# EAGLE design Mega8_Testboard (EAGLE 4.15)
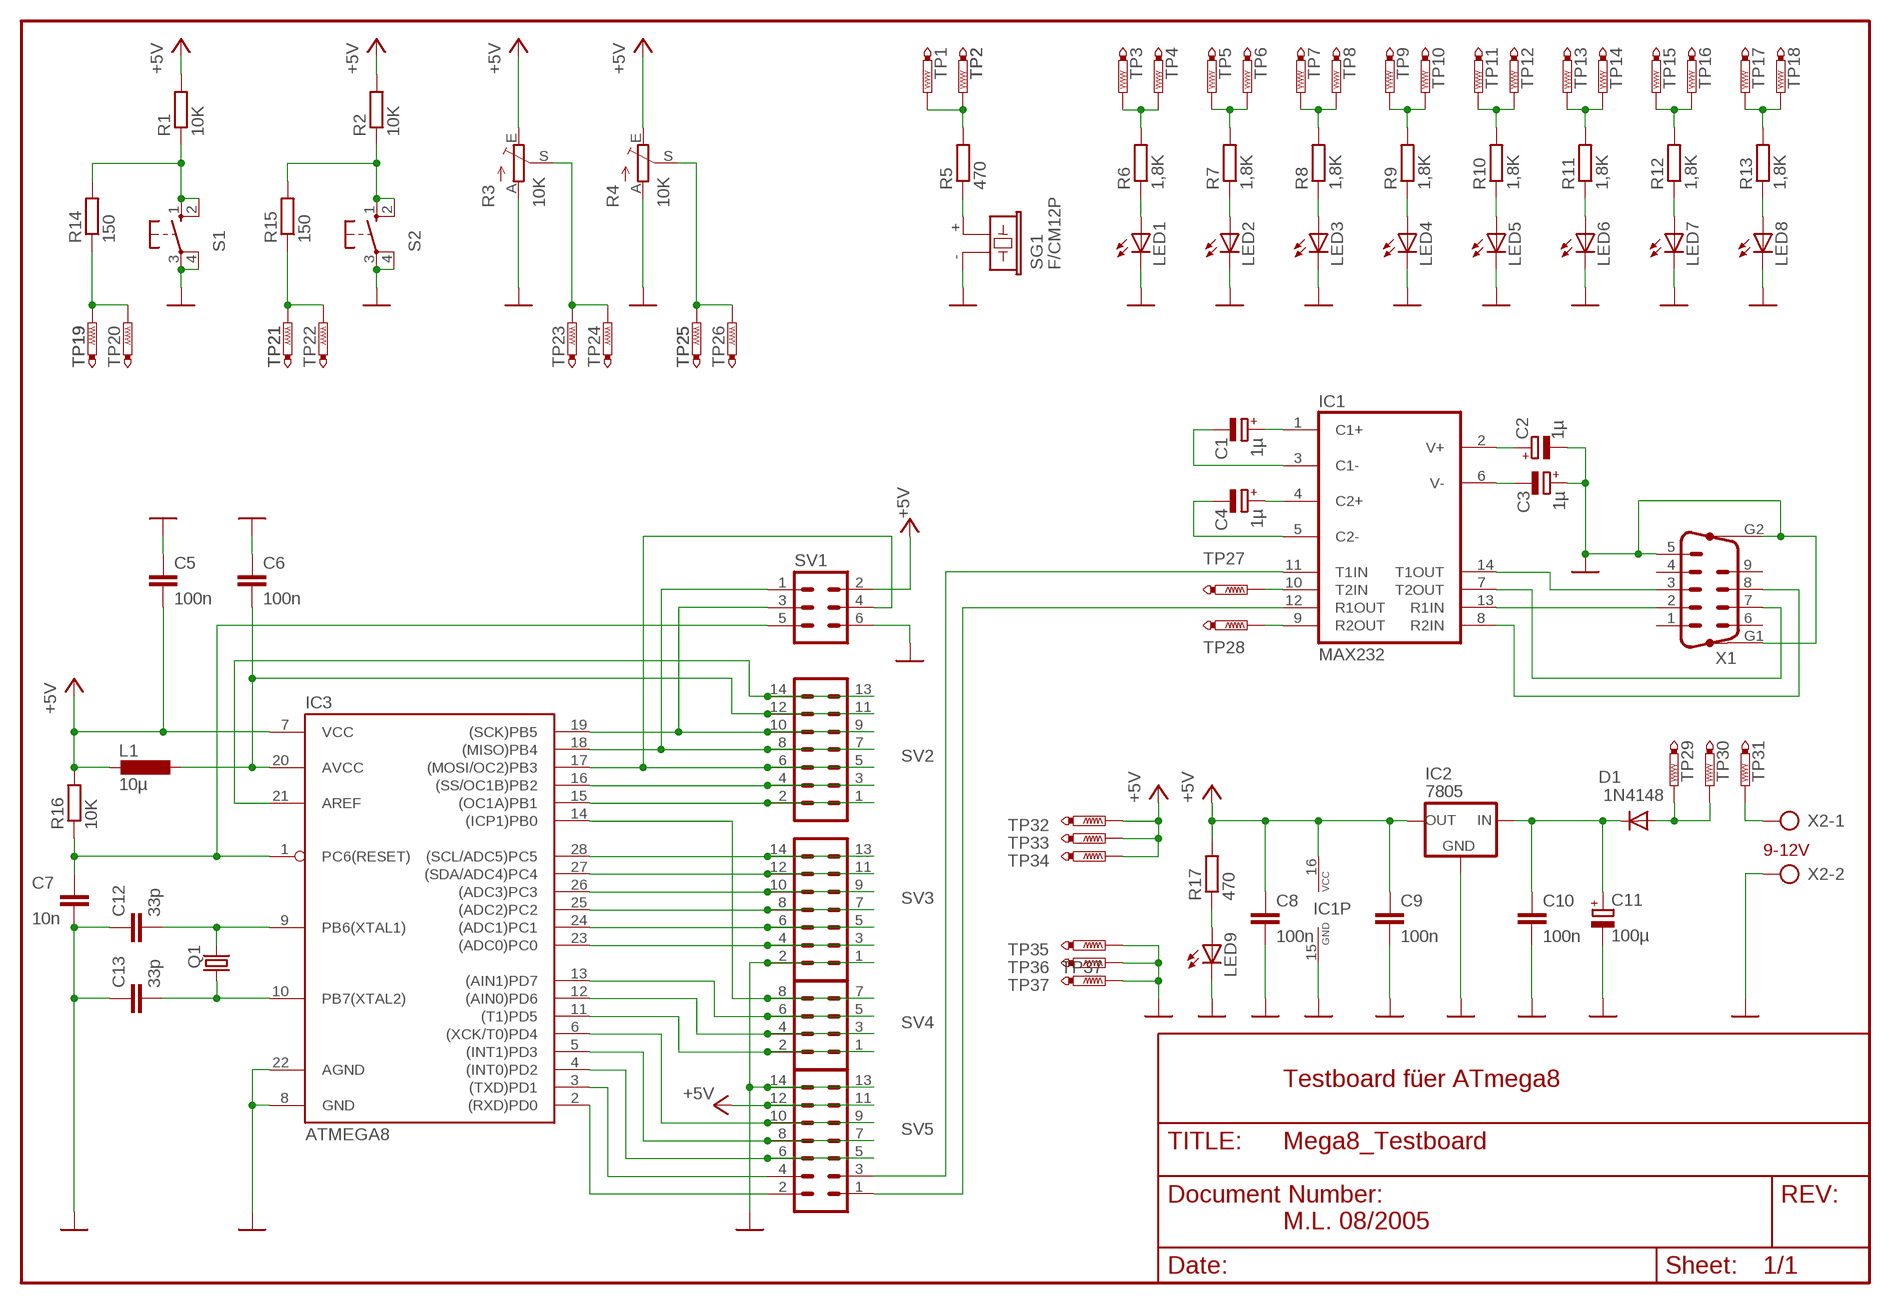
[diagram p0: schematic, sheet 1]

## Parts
C1  1µ  CPOL-EUE2-5  [E2-5]
C2  1µ  CPOL-EUE2-5  [E2-5]
C3  1µ  CPOL-EUE2-5  [E2-5]
C4  1µ  CPOL-EUE2-5  [E2-5]
C5  100n  C-EU050-025X075  [C050-025X075]
C6  100n  C-EU050-025X075  [C050-025X075]
C7  10n  C-EU050-025X075  [C050-025X075]
C8  100n  C-EU050-025X075  [C050-025X075]
C9  100n  C-EU050-025X075  [C050-025X075]
C10  100n  C-EU050-025X075  [C050-025X075]
C11  100µ  CPOL-EUE5-10.5  [E5-10,5]
C12  33p  C-EU050-025X075  [C050-025X075]
C13  33p  C-EU050-025X075  [C050-025X075]
D1  1N4148  [DO35-10]
IC1  MAX232  [DIL16]
IC2  7805  78XXS  [78XXS]
IC3  ATMEGA8  [28P_DIL]
L1  10µ  L-EU0207/10  [0207/10]
LED1  LEDSFH482  [SFH482]
LED2  LEDSFH482  [SFH482]
LED3  LEDSFH482  [SFH482]
LED4  LEDSFH482  [SFH482]
LED5  LEDSFH482  [SFH482]
LED6  LEDSFH482  [SFH482]
LED7  LEDSFH482  [SFH482]
LED8  LEDSFH482  [SFH482]
LED9  LEDSFH482  [SFH482]
Q1  CRYTALHC49S  [HC49/S]
R1  10K  R-EU_0207/10  [0207/10]
R2  10K  R-EU_0207/10  [0207/10]
R3  10K  TRIM_EU-CA9V  [CA9V]
R4  10K  TRIM_EU-CA9V  [CA9V]
R5  470  R-EU_0207/10  [0207/10]
R6  1,8K  R-EU_0207/10  [0207/10]
R7  1,8K  R-EU_0207/10  [0207/10]
R8  1,8K  R-EU_0207/10  [0207/10]
R9  1,8K  R-EU_0207/10  [0207/10]
R10  1,8K  R-EU_0207/10  [0207/10]
R11  1,8K  R-EU_0207/10  [0207/10]
R12  1,8K  R-EU_0207/10  [0207/10]
R13  1,8K  R-EU_0207/10  [0207/10]
R14  150  R-EU_0207/10  [0207/10]
R15  150  R-EU_0207/10  [0207/10]
R16  10K  R-EU_0207/10  [0207/10]
R17  470  R-EU_0207/10  [0207/10]
S1  40-XX  [B3F-40XX]
S2  40-XX  [B3F-40XX]
SG1  F/CM12P  [F/CM12P]
SV1  MA03-2  [MA03-2]
SV2  MA07-2  [MA07-2]
SV3  MA07-2  [MA07-2]
SV4  MA04-2  [MA04-2]
SV5  MA07-2  [MA07-2]
TP1  PTR1PAD1-13  [P1-13]
TP2  PTR1PAD1-13  [P1-13]
TP3  PTR1PAD1-13  [P1-13]
TP4  PTR1PAD1-13  [P1-13]
TP5  PTR1PAD1-13  [P1-13]
TP6  PTR1PAD1-13  [P1-13]
TP7  PTR1PAD1-13  [P1-13]
TP8  PTR1PAD1-13  [P1-13]
TP9  PTR1PAD1-13  [P1-13]
TP10  PTR1PAD1-13  [P1-13]
TP11  PTR1PAD1-13  [P1-13]
TP12  PTR1PAD1-13  [P1-13]
TP13  PTR1PAD1-13  [P1-13]
TP14  PTR1PAD1-13  [P1-13]
TP15  PTR1PAD1-13  [P1-13]
TP16  PTR1PAD1-13  [P1-13]
TP17  PTR1PAD1-13  [P1-13]
TP18  PTR1PAD1-13  [P1-13]
TP19  PTR1PAD1-13  [P1-13]
TP20  PTR1PAD1-13  [P1-13]
TP21  PTR1PAD1-13  [P1-13]
TP22  PTR1PAD1-13  [P1-13]
TP23  PTR1PAD1-13  [P1-13]
TP24  PTR1PAD1-13  [P1-13]
TP25  PTR1PAD1-13  [P1-13]
TP26  PTR1PAD1-13  [P1-13]
TP27  PTR1PAD1-13  [P1-13]
TP28  PTR1PAD1-13  [P1-13]
TP29  PTR1PAD1-13  [P1-13]
TP30  PTR1PAD1-13  [P1-13]
TP31  PTR1PAD1-13  [P1-13]
TP32  PTR1PAD1-13  [P1-13]
TP33  PTR1PAD1-13  [P1-13]
TP34  PTR1PAD1-13  [P1-13]
TP35  PTR1PAD1-13  [P1-13]
TP36  PTR1PAD1-13  [P1-13]
TP37  PTR1PAD1-13  [P1-13]
X1  M09HP  [M09HP]
X2  AK300/2  [AK300/2]

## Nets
+5V: C5.2 C8.1 C9.1 IC1.16(VCC) IC2.OUT IC3.7(VCC) L1.2 R1.2 R2.2 R3.E R4.E R16.2 R17.2 SV1.2 SV5.11 SV5.12 TP32.1(TP) TP33.1(TP) TP34.1(TP)
AREF: IC3.21(AREF) SV2.13 SV2.14
AVCC: C6.2 IC3.20(AVCC) L1.1 SV2.11 SV2.12
GND: C2.- C3.+ C5.1 C6.1 C7.2 C8.2 C9.2 C10.2 C11.- C12.1 C13.1 IC1.15(GND) IC2.GND IC3.8(GND) IC3.22(AGND) LED1.K(C) LED2.K(C) LED3.K(C) LED4.K(C) LED5.K(C) LED6.K(C) LED7.K(C) LED8.K(C) LED9.K(C) R3.A R4.A S1.3(P) S1.4(P1) S2.3(P) S2.4(P1) SG1.- SV1.6 SV3.1 SV3.2 SV5.13 SV5.14 TP35.1(TP) TP36.1(TP) TP37.1(TP) X1.5 X1.G1 X1.G2 X2.2
N$1: C1.+ IC1.1(C1+)
N$2: C1.- IC1.3(C1-)
N$3: C4.+ IC1.4(C2+)
N$4: C4.- IC1.5(C2-)
N$5: C2.+ IC1.2(V+)
N$6: C3.- IC1.6(V-)
N$7: IC1.14(T1OUT) X1.3
N$8: IC1.13(R1IN) X1.2
N$9: R3.S TP23.1(TP) TP24.1(TP)
N$10: LED9.A R17.1
N$11: C10.1 C11.+ D1.C IC2.IN
N$12: TP31.1(TP) X2.1
N$13: D1.A TP29.1(TP) TP30.1(TP)
N$14: R4.S TP25.1(TP) TP26.1(TP)
N$15: R6.2 TP3.1(TP) TP4.1(TP)
N$16: LED1.A R6.1
N$17: LED2.A R7.1
N$18: LED3.A R8.1
N$19: R7.2 TP5.1(TP) TP6.1(TP)
N$20: LED4.A R9.1
N$21: LED5.A R10.1
N$22: LED6.A R11.1
N$23: R8.2 TP7.1(TP) TP8.1(TP)
N$24: LED7.A R12.1
N$25: LED8.A R13.1
N$26: IC1.7(T2OUT) X1.7
N$27: R9.2 TP9.1(TP) TP10.1(TP)
N$28: IC1.10(T2IN) TP27.1(TP)
N$29: IC1.8(R2IN) X1.8
N$30: IC1.9(R2OUT) TP28.1(TP)
N$31: R10.2 TP11.1(TP) TP12.1(TP)
N$32: R11.2 TP13.1(TP) TP14.1(TP)
N$33: R12.2 TP15.1(TP) TP16.1(TP)
N$34: R5.1 SG1.+
N$35: R13.2 TP17.1(TP) TP18.1(TP)
N$36: IC1.12(R1OUT) SV5.1
N$37: IC1.11(T1IN) SV5.3
N$40: R14.1 TP19.1(TP) TP20.1(TP)
N$41: R15.1 TP21.1(TP) TP22.1(TP)
N$45: R1.1 R14.2 S1.1(S) S1.2(S1)
N$47: R2.1 R15.2 S2.1(S) S2.2(S1)
N$48: R5.2 TP1.1(TP) TP2.1(TP)
N$50: IC3.2((RXD)PD0) SV5.2
N$51: C12.2 IC3.9(PB6(XTAL1)) Q1.2
N$52: C13.2 IC3.10(PB7(XTAL2)) Q1.1
N$53: IC3.3((TXD)PD1) SV5.4
N$54: IC3.4((INT0)PD2) SV5.5 SV5.6
N$55: IC3.5((INT1)PD3) SV5.7 SV5.8
N$56: IC3.6((XCK/T0)PD4) SV5.9 SV5.10
N$57: IC3.11((T1)PD5) SV4.1 SV4.2
N$58: C7.1 IC3.1(PC6(RESET)) R16.1 SV1.5
N$59: IC3.12((AIN0)PD6) SV4.3 SV4.4
N$60: IC3.13((AIN1)PD7) SV4.5 SV4.6
N$61: IC3.14((ICP1)PB0) SV4.7 SV4.8
N$62: IC3.15((OC1A)PB1) SV2.1 SV2.2
N$63: IC3.16((SS/OC1B)PB2) SV2.3 SV2.4
N$64: IC3.17((MOSI/OC2)PB3) SV1.4 SV2.5 SV2.6
N$65: IC3.18((MISO)PB4) SV1.1 SV2.7 SV2.8
N$66: IC3.19((SCK)PB5) SV1.3 SV2.9 SV2.10
N$67: IC3.23((ADC0)PC0) SV3.3 SV3.4
N$69: IC3.24((ADC1)PC1) SV3.5 SV3.6
N$70: IC3.25((ADC2)PC2) SV3.7 SV3.8
N$71: IC3.26((ADC3)PC3) SV3.9 SV3.10
N$72: IC3.27((SDA/ADC4)PC4) SV3.11 SV3.12
N$73: IC3.28((SCL/ADC5)PC5) SV3.13 SV3.14
Unconnected: X1.1 X1.4 X1.6 X1.9

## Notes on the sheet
- 9-12V
- Testboard füer ATmega8
- M.L. 08/2005

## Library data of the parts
C1-C4 C11 = RCL:CPOL-EU: POLARIZED CAPACITOR, European symbol
C5-C10 C12 C13 = RCL:C-EU: CAPACITOR, European symbol
D1 = diode:1N4148: DIODE
IC1 = maxim:MAX232: RS232 TRANSEIVER
IC2 = v-reg:78XXS: VOLTAGE REGULATOR
IC3 = MANNI:ATMEGA8: 8-bit AVR with 8KBytes In-System Programmable Flash ATmega8(L)
L1 = RCL:L-EU: INDUCTOR, European symbol
LED1-LED9 = led:LED: LED
Q1 = crystal:CRYTAL: CRYSTAL
R1 R2 R5-R17 = RCL:R-EU_: RESISTOR, European symbol
R3 R4 = pot:TRIM_EU-: POTENTIOMETER
S1 S2 = switch-omron:40-XX: OMRON SWITCH
SG1 = buzzer:F/CM12P: BUZZER
SV1 = con-lstb:MA03-2: PIN HEADER
SV2 SV3 SV5 = con-lstb:MA07-2: PIN HEADER
SV4 = con-lstb:MA04-2: PIN HEADER
TP1-TP37 = testpad:PTR1: TEST PIN
X1 = con-subd:M09HP: SUB-D
X2 = con-ptr500:AK300/2: CONNECTOR

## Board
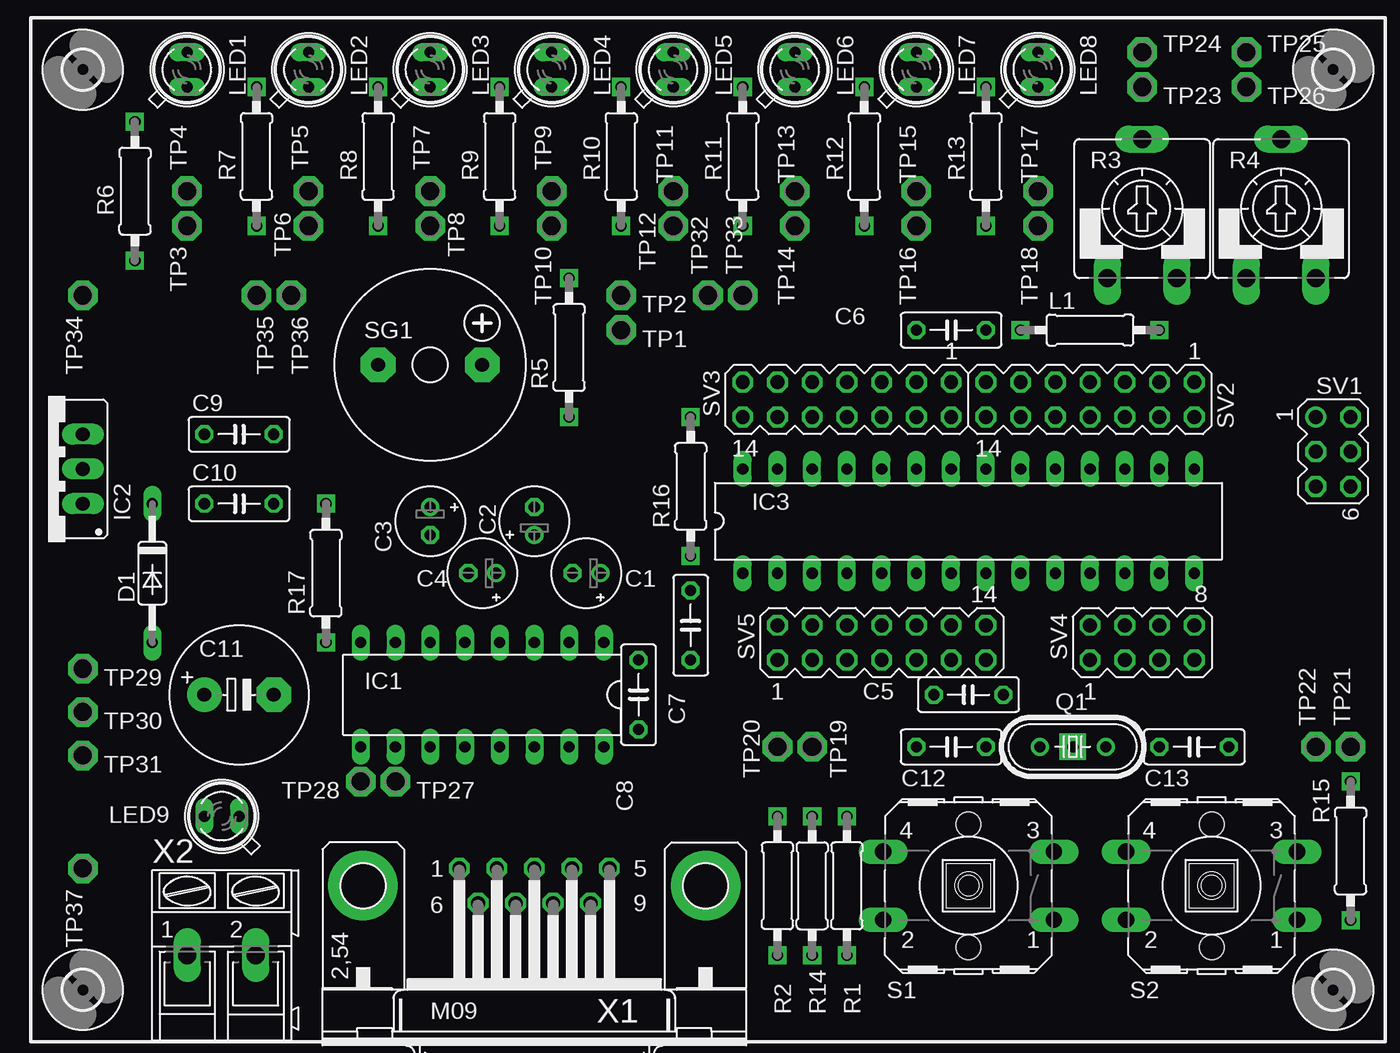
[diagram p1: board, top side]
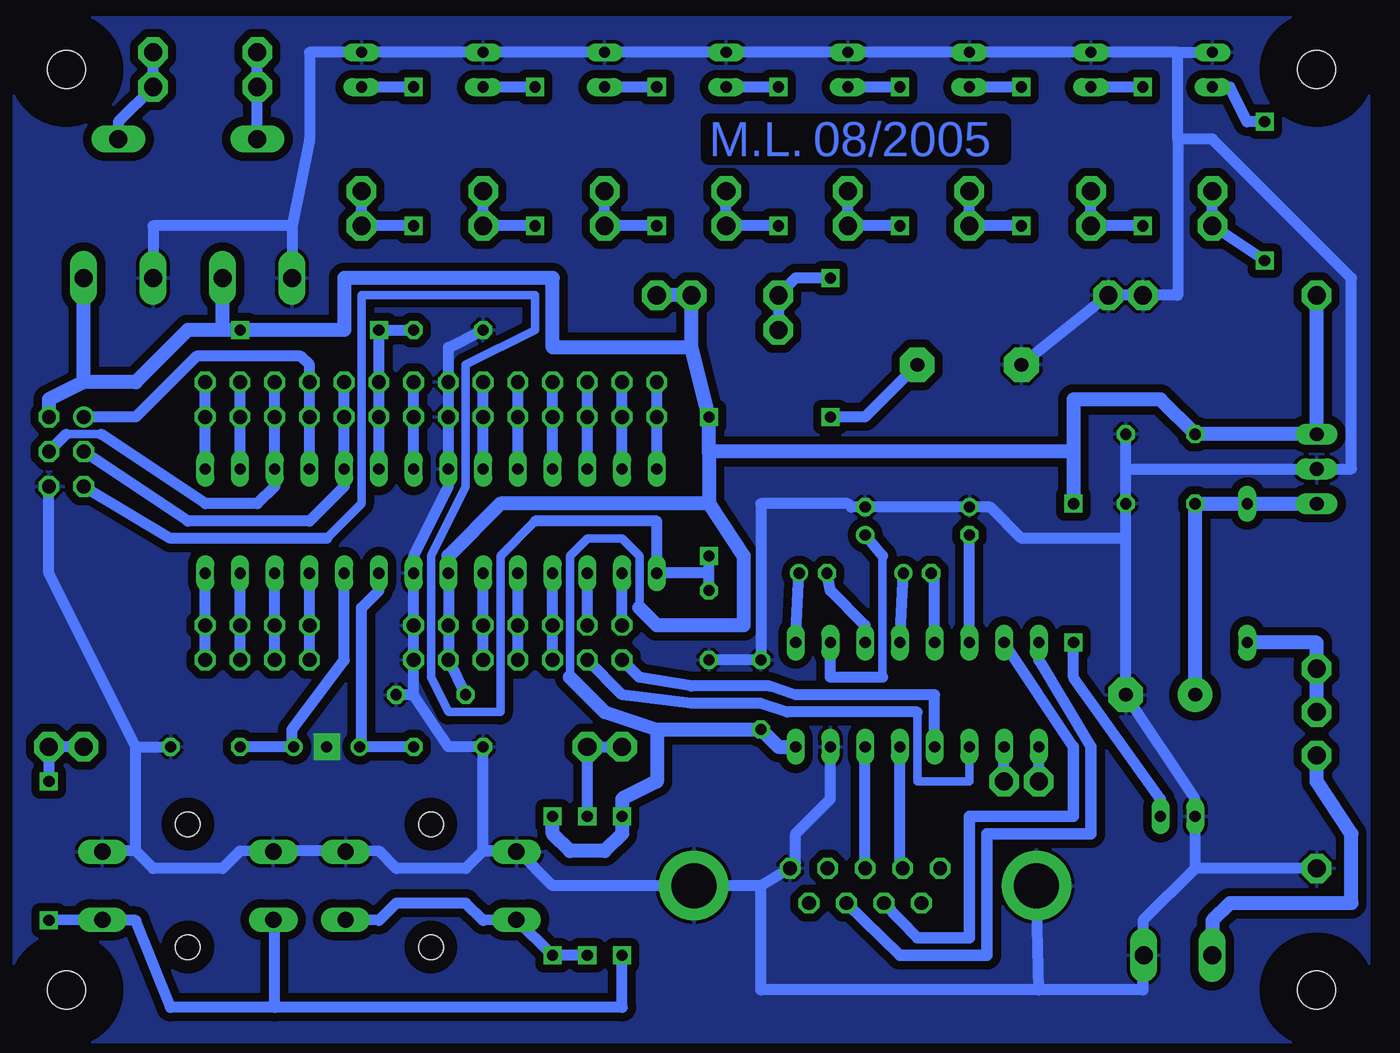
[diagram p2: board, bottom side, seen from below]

No outline drawn. Coordinates in mm, seen from the top.
Copper layers (1*16): Top 0.035mm / dielectric 1.5mm / Bottom 0.035mm
Design rules "default": minimum track width 10mil, minimum drill 24mil, track to track 8mil, track to pad 8mil, pad to pad 8mil, via to via 8mil, smd to smd 8mil, copper to edge 40mil, drill to drill 8mil, minimum pad ring 10mil, minimum via ring 8mil, stop-mask expansion 4mil, vias tented up to drill 0mil, thermal gap 10mil

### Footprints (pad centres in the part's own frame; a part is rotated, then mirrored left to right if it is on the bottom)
E2-5 = drill 0.813 pad 1.27 round: + -1.016,0 | drill 0.813 pad 1.27 octagon: - 1.016,0
C050-025X075 = drill 0.813 octagon: 1 -2.54,0; 2 2.54,0
E5-10,5 = drill 1.016 pad 2.54 round: + -2.54,0 | drill 1.016 pad 2.54 octagon: - 2.54,0
DO35-10 = drill 0.813 long: A 5.08,0; C -5.08,0
DIL16 = drill 0.813 long: 1 -8.89,-3.81; 2 -6.35,-3.81; 3 -3.81,-3.81; 4 -1.27,-3.81; 5 1.27,-3.81; 6 3.81,-3.81; 7 6.35,-3.81; 8 8.89,-3.81; 9 8.89,3.81; 10 6.35,3.81; 11 3.81,3.81; 12 1.27,3.81; 13 -1.27,3.81; 14 -3.81,3.81; 15 -6.35,3.81; 16 -8.89,3.81
78XXS = drill 1.016 long: GND 0,-2.54; IN -2.54,-2.54; OUT 2.54,-2.54
28P_DIL = drill 0.813 long: 1 -15.24,-3.81; 2 -12.7,-3.81; 3 -10.16,-3.81; 4 -7.62,-3.81; 5 -5.08,-3.81; 6 -2.54,-3.81; 7 0,-3.81; 8 2.54,-3.81; 9 5.08,-3.81; 10 7.62,-3.81; 11 10.16,-3.81; 12 12.7,-3.81; 13 15.24,-3.81; 14 17.78,-3.81; 15 17.78,3.81; 16 15.24,3.81; 17 12.7,3.81; 18 10.16,3.81; 19 7.62,3.81; 20 5.08,3.81; 21 2.54,3.81; 22 0,3.81; 23 -2.54,3.81; 24 -5.08,3.81; 25 -7.62,3.81; 26 -10.16,3.81; 27 -12.7,3.81; 28 -15.24,3.81
0207/10 = drill 0.813 square: 1 -5.08,0; 2 5.08,0
SFH482 = drill 0.813 long: A -1.27,0; K 1.27,0
HC49/S = drill 0.813 round: 1 -2.413,0; 2 2.413,0
CA9V = drill 1.321 long: A -2.54,-5.08; E 2.54,-5.08; S 0,5.08
B3F-40XX = drill 1.194 long: 1 -6.248,2.489; 2 6.248,2.489; 3 -6.248,-2.489; 4 6.248,-2.489 | hole 1.803: 0,-4.496; 0,4.496
F/CM12P = drill 1.016 pad 2.54 octagon: + 3.81,0; - -3.81,0
MA03-2 = drill 1.016 round: 1 -2.54,-1.27 | drill 1.016 octagon: 2 -2.54,1.27; 3 0,-1.27; 4 0,1.27; 5 2.54,-1.27; 6 2.54,1.27
MA07-2 = drill 1.016 octagon: 1 -7.62,-1.27; 2 -7.62,1.27; 3 -5.08,-1.27; 4 -5.08,1.27; 5 -2.54,-1.27; 6 -2.54,1.27; 7 0,-1.27; 8 0,1.27; 9 2.54,-1.27; 10 2.54,1.27; 11 5.08,-1.27; 12 5.08,1.27; 13 7.62,-1.27; 14 7.62,1.27
MA04-2 = drill 1.016 octagon: 1 -3.81,-1.27; 2 -3.81,1.27; 3 -1.27,-1.27; 4 -1.27,1.27; 5 1.27,-1.27; 6 1.27,1.27; 7 3.81,-1.27; 8 3.81,1.27
P1-13 = drill 1.321 pad 2.159 octagon: 1 0,0
2,8 = hole 2.8: 0,0
M09HP = drill 1.016 octagon: 1 -5.486,1.27; 2 -2.743,1.27; 3 0,1.27; 4 2.743,1.27; 5 5.486,1.27; 6 -4.115,-1.27; 7 -1.372,-1.27; 8 1.372,-1.27; 9 4.115,-1.27 | drill 3.302 pad 5.08 round: G1 -12.522,0; G2 12.522,0
AK300/2 = drill 1.321 long: 1 -2.515,0; 2 2.489,0

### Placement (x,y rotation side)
C1  40.64,34.29 180 top
C2  36.83,38.1 90 top
C3  29.21,38.1 270 top
C4  33.02,34.29 180 top
C5  68.58,25.4 180 top
C6  67.31,52.07 0 top
C7  48.26,30.48 270 top
C8  44.45,25.4 90 top
C9  15.24,44.45 0 top
C10  15.24,39.37 0 top
C11  15.24,25.4 0 top
C12  67.31,21.59 0 top
C13  85.09,21.59 180 top
D1  8.89,34.29 270 top
IC1  33.02,25.4 180 top
IC2  1.27,41.91 90 top
IC3  67.31,38.1 0 top
L1  77.47,52.07 0 top
LED1  11.43,71.12 90 top
LED2  20.32,71.12 90 top
LED3  29.21,71.12 90 top
LED4  38.1,71.12 90 top
LED5  46.99,71.12 90 top
LED6  55.88,71.12 90 top
LED7  64.77,71.12 90 top
LED8  73.66,71.12 90 top
LED9  13.97,16.51 180 top
Q1  76.2,21.59 180 top
R1  59.69,11.43 90 top
R2  54.61,11.43 90 top
R3  81.28,60.96 0 top
R4  91.44,60.96 0 top
R5  39.37,50.8 90 top
R6  7.62,62.23 270 top
R7  16.51,64.77 270 top
R8  25.4,64.77 270 top
R9  34.29,64.77 270 top
R10  43.18,64.77 270 top
R11  52.07,64.77 270 top
R12  60.96,64.77 270 top
R13  69.85,64.77 270 top
R14  57.15,11.43 270 top
R15  96.52,13.97 270 top
R16  48.26,40.64 90 top
R17  21.59,34.29 90 top
S1  68.58,11.43 180 top
S2  86.36,11.43 180 top
SG1  29.21,49.53 0 top
SV1  95.25,43.18 270 top
SV2  77.47,46.99 180 top
SV3  59.69,46.99 180 top
SV4  81.28,29.21 0 top
SV5  62.23,29.21 0 top
TP1  43.18,52.07 180 top
TP2  43.18,54.61 180 top
TP3  11.43,59.69 180 top
TP4  11.43,62.23 180 top
TP5  20.32,62.23 180 top
TP6  20.32,59.69 180 top
TP7  29.21,62.23 180 top
TP8  29.21,59.69 180 top
TP9  38.1,62.23 180 top
TP10  38.1,59.69 180 top
TP11  46.99,62.23 180 top
TP12  46.99,59.69 180 top
TP13  55.88,62.23 180 top
TP14  55.88,59.69 180 top
TP15  64.77,62.23 180 top
TP16  64.77,59.69 180 top
TP17  73.66,62.23 180 top
TP18  73.66,59.69 180 top
TP19  57.15,21.59 270 top
TP20  54.61,21.59 270 top
TP21  96.52,21.59 0 top
TP22  93.98,21.59 0 top
TP23  81.28,69.85 270 top
TP24  81.28,72.39 90 top
TP25  88.9,72.39 270 top
TP26  88.9,69.85 270 top
TP27  26.67,19.05 270 top
TP28  24.13,19.05 270 top
TP29  3.81,27.3 0 top
TP30  3.81,24.13 0 top
TP31  3.81,20.95 0 top
TP32  49.53,54.61 270 top
TP33  52.07,54.61 270 top
TP34  3.81,54.61 90 top
TP35  16.51,54.61 90 top
TP36  19.05,54.61 90 top
TP37  3.81,12.7 90 top
U$2  [2,8]  3.81,3.81 0 top
U$3  [2,8]  95.25,3.81 0 top
U$4  [2,8]  95.25,71.12 0 top
U$5  [2,8]  3.81,71.12 0 top
X1  36.83,11.43 0 top
X2  13.97,6.35 0 top

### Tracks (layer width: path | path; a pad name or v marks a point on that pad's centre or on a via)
+5V
  Bottom 0.61: 58.42,26.67 58.42,35.56 57.15,36.83 54.61,36.83 53.34,35.56 53.34,31.75
  Bottom 0.813: 67.31,35.56 IC3.7 SV5.12 SV5.11 C5.2
  Bottom 1.016: IC1.16 43.18,21.59 C8.1 52.07,22.86 | 67.31,35.56 63.5,39.37 48.26,39.37 | 93.98,48.26 96.52,46.99 SV1.2 | 21.59,43.18 48.26,43.18 | 53.34,31.75 52.07,30.48 45.72,30.48 45.72,35.56 48.26,39.37 | 21.59,43.18 21.59,46.99 15.24,46.99 C9.1 IC2.OUT TP34.1 | 21.59,43.18 R17.2 | 48.26,43.18 48.26,39.37 | R1.2 59.69,15.24 58.42,13.97 55.88,13.97 54.61,15.24 R2.2 54.61,17.78 52.07,19.05 52.07,22.86 | TP33.1 TP32.1 49.53,50.8 | 48.26,43.18 R16.2 49.53,50.8 | 83.82,52.07 L1.2 74.93,52.07 74.93,55.88 59.69,55.88 59.69,50.8 49.53,50.8 | 83.82,52.07 R3.E | 93.98,48.26 R4.E | 83.82,52.07 86.36,52.07 90.17,48.26 93.98,48.26 | 58.42,26.67 55.88,24.13 52.07,22.86
AREF
  Bottom 0.813: SV2.13 SV2.14 IC3.21
AVCC
  Bottom 0.813: IC3.20 SV2.12 SV2.11 L1.1 C6.2
GND  (via drill 0.8 pad 1.93)
  Bottom 0.813: 17.78,41.91 C10.2 17.78,36.83 | TP37.1 12.7,12.7 | 12.7,17.78 LED9.K 12.7,12.7 | 16.51,8.89 16.51,6.35 X2.2 16.51,3.81 | 69.85,35.56 67.31,40.64 IC3.22 SV3.2 SV3.1 67.31,50.8 C6.1 | 69.85,35.56 IC3.8 SV5.14 SV5.13 | 64.77,13.97 S1.4 | 90.17,13.97 S2.3 | 90.17,13.97 92.71,13.97 | SV5.13 69.85,35.56 | 62.23,13.97 62.28,13.97 S1.4 | 44.45,11.43 44.45,3.81 24.13,3.81 | 16.51,3.81 24.13,3.81 | 16.51,8.89 16.51,3.81 | 12.7,12.7 16.51,8.89 | 12.7,12.7 12.7,17.78 | 12.7,17.78 C11.- 17.78,36.83 | 90.17,13.97 90.17,21.59 | IC1.15 39.37,17.78 41.91,15.24 41.91,13.11 X1.5 44.45,11.43 | 17.78,36.83 25.4,36.83 27.69,39.12 C3.+ 29.21,39.37 29.46,39.12 C2.- 37.85,39.12 38.1,39.37 44.45,39.37 C8.2 C7.2 | 69.85,25.4 SV5.13 | 69.85,25.4 C5.1 | 64.77,13.97 66.04,12.7 71.12,12.7 72.39,13.97 S1.3 76.2,13.97 80.01,13.97 S2.4 82.55,13.97 83.82,12.7 88.9,12.7 90.17,13.97 | 69.85,25.4 67.31,21.59 C12.1 64.77,13.97 | 90.17,21.59 C13.1 | 62.23,13.97 59.69,11.43 X1.G2 44.45,11.43 | 62.23,13.97 64.77,13.97 | 62.23,13.97 S1.4 | 13.97,72.39 LED2.K LED3.K LED4.K LED5.K LED6.K LED7.K LED8.K 77.47,72.39 77.47,66.04 78.74,59.69 | 13.97,72.39 LED1.K | TP35.1 TP36.1 | TP36.1 SG1.- TP36.1 | 78.74,59.69 88.9,59.69 R4.A | 78.74,59.69 R3.A | 17.78,41.91 C9.2 | 17.78,41.91 IC2.GND 1.27,41.91 1.27,55.88 11.43,66.04 13.97,66.04 | 13.97,66.04 13.97,72.39 | TP35.1 TP36.1 | TP35.1 13.97,54.61 13.97,66.04 | 24.13,3.81 X1.G1 | SV1.6 96.52,34.29 90.17,21.59
  other vias: 76.2,21.59
  pour Bottom (isolate 0.61): 0,0 99.06,0 99.06,74.93 0,74.93
N$1
  Bottom 0.813: IC1.1 C1.+
N$2
  Bottom 0.813: C1.- 39.37,33.02 36.83,30.48 IC1.3
N$3
  Bottom 0.813: IC1.4 C4.+
N$4
  Bottom 0.813: C4.- 31.75,34.29 IC1.5
N$5
  Bottom 0.61: 35.56,26.67 35.56,35.56
  Bottom 0.813: 35.56,35.56 C2.+ | 35.56,26.67 39.37,26.67 IC1.2
N$6
  Bottom 0.813: IC1.6 C3.-
N$7
  Bottom 0.813: X1.3 IC1.14
N$8
  Bottom 0.813: X1.2 34.29,12.9 IC1.13
N$9
  Bottom 0.813: R3.S TP23.1 TP24.1
N$10
  Bottom 0.813: LED9.A 15.24,17.78 21.59,26.67 R17.1
N$11
  Bottom 1.016: IC2.IN D1.C C10.1 C11.+
N$12
  Bottom 1.016: X2.1 11.43,8.89 10.16,10.16 1.27,10.16 1.27,15.24 3.81,19.05 TP31.1
N$13
  Bottom 1.016: D1.A 3.81,29.21 TP29.1 TP30.1
N$14
  Bottom 0.813: TP25.1 TP26.1 91.44,67.31 R4.S
N$15
  Bottom 0.813: TP4.1 TP3.1 R6.2
N$16
  Bottom 0.813: R6.1 8.89,67.31 10.16,69.85 LED1.A
N$17
  Bottom 0.813: R7.1 LED2.A
N$18
  Bottom 0.813: R8.1 LED3.A
N$19
  Bottom 0.813: TP5.1 TP6.1 R7.2
N$20
  Bottom 0.813: R9.1 LED4.A
N$21
  Bottom 0.813: R10.1 LED5.A
N$22
  Bottom 0.813: R11.1 LED6.A
N$23
  Bottom 0.813: TP7.1 TP8.1 R8.2
N$24
  Bottom 0.813: R12.1 LED7.A
N$25
  Bottom 0.813: R13.1 LED8.A
N$26
  Bottom 0.813: 21.59,21.59 IC1.7 | 33.02,7.62 X1.7
  Bottom 0.852: 21.59,21.59 21.59,16.51 29.21,16.51 29.21,7.62 33.02,7.62
N$27
  Bottom 0.813: R9.2 TP10.1 TP9.1
N$28
  Bottom 0.813: TP27.1 IC1.10
N$29
  Bottom 0.813: IC1.8 24.13,27.94 20.32,21.59 | 34.29,6.35 X1.8
  Bottom 0.852: 20.32,21.59 20.32,15.24 27.94,15.24 27.94,6.35 34.29,6.35
N$30
  Bottom 0.813: TP28.1 IC1.9
N$31
  Bottom 0.813: R10.2 TP12.1 TP11.1
N$32
  Bottom 0.813: R11.2 TP14.1 TP13.1
N$33
  Bottom 0.813: R12.2 TP16.1 TP15.1
N$34
  Bottom 0.813: SG1.+ 36.83,45.72 R5.1
N$35
  Bottom 0.813: R13.2 TP18.1 TP17.1
N$36
  Bottom 0.813: SV5.1 53.34,26.67 49.53,26.04 43.81,26.04 41.91,25.4 31.75,25.4 IC1.12
N$37
  Bottom 0.61: IC1.11 29.21,19.05 33.02,19.05 33.02,24.13
  Bottom 0.813: 33.02,24.13 42.55,24.13 44.45,24.77 49.53,24.77 54.61,25.4 SV5.3
N$40
  Bottom 0.813: TP20.1 TP19.1 R14.1
N$41
  Bottom 0.813: TP22.1 TP21.1 R15.1
N$45
  Bottom 0.813: S1.1 72.39,8.89 71.12,10.16 66.04,10.16 64.77,8.89 S1.2 R1.1 R14.2
N$47
  Bottom 0.813: R2.1 54.61,2.54 80.01,2.54 | R15.2 S2.1 92.71,8.89 90.17,8.89 87.63,2.54 80.01,2.54 | S2.2 80.01,8.94 80.01,2.54
N$48
  Bottom 0.813: TP1.1 TP2.1 41.91,55.88 R5.2
N$50
  Bottom 0.813: SV5.2 IC3.2
N$51
  Bottom 0.813: 73.66,21.59 73.66,31.75 72.39,33.02 IC3.9 | 73.66,21.59 Q1.2 | C12.2 73.66,21.59
N$52
  Bottom 0.813: IC3.10 74.93,27.94 78.74,22.86 78.74,21.59 | Q1.1 78.74,21.59 | 78.74,21.59 C13.2
N$53
  Bottom 0.813: SV5.4 IC3.3
N$54
  Bottom 0.813: SV5.5 SV5.6 IC3.4
N$55
  Bottom 0.813: SV5.7 SV5.8 IC3.5
N$56
  Bottom 0.813: SV5.9 SV5.10 IC3.6
N$57
  Bottom 0.813: SV4.1 SV4.2 IC3.11
N$58
  Bottom 0.61: 60.96,38.1 63.5,35.56 63.5,24.13 67.31,24.13 68.58,26.67 68.58,35.56 66.04,40.64 66.04,49.53 60.96,52.07 60.96,54.61 73.66,54.61 73.66,39.37 76.2,36.83
  Bottom 0.813: C7.1 48.26,34.29 | 48.26,34.29 R16.1 | 48.26,34.29 IC3.1 52.07,38.1 60.96,38.1 | 76.2,36.83 87.63,36.83 SV1.5
N$59
  Bottom 0.813: SV4.3 SV4.4 IC3.12
N$60
  Bottom 0.813: SV4.5 SV4.6 IC3.13
N$61
  Bottom 0.813: SV4.7 SV4.8 IC3.14
N$62
  Bottom 0.813: SV2.1 SV2.2 IC3.15
N$63
  Bottom 0.813: IC3.16 SV2.4 SV2.3
N$64
  Bottom 0.61: 92.71,44.45 95.25,44.45
  Bottom 0.813: SV2.5 SV2.6 IC3.17 80.01,40.64 81.28,39.37 85.09,39.37 92.71,44.45 | 95.25,44.45 SV1.4
N$65
  Bottom 0.813: IC3.18 SV2.8 SV2.7 77.47,49.53 78.11,50.16 85.72,50.16 90.17,45.72 SV1.1
N$66
  Bottom 0.813: SV2.9 SV2.10 IC3.19 74.93,40.64 77.47,38.1 86.36,38.1 SV1.3
N$67
  Bottom 0.813: SV3.3 SV3.4 IC3.23
N$69
  Bottom 0.813: SV3.5 SV3.6 IC3.24
N$70
  Bottom 0.813: SV3.7 SV3.8 IC3.25
N$71
  Bottom 0.813: SV3.9 SV3.10 IC3.26
N$72
  Bottom 0.813: SV3.11 SV3.12 IC3.27
N$73
  Bottom 0.813: SV3.13 SV3.14 IC3.28

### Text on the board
Bottom: 08/2005 | M.L.
Beschriftung: LED1 | LED2 | LED3 | LED4 | LED5 | LED6 | LED7 | LED8 | Poti1 | Poti2 | + 5V | + 5V | GND | Poti1 | Poti2 | Piezo | PC5 | PC4 | PC3 | PC2 | PC1 | PC0 | AGND | AREF | AVCC | PB5 | PB4 | PB3 | PB2 | PB1 | Piezo | ISP | PD0 | PD1 | PD2 | PD3 | PD4 | VCC | GND | PD5 | PD6 | PD7 | PB0 | Aus | TX | RX | Ein | Taster1 | Quarz | Taster2 | TX2 | RX2 | GND | Taster1 | Taster2 | RS232 | + | GND | 7,2 - 12V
